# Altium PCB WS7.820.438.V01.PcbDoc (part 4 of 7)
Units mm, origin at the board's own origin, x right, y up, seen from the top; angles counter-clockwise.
Board outline 143.01 x 224 mm, 4 copper layers (Top Layer, G2, S3, Bottom Layer); 863 components, 638 nets, 2623 pads, 4664 vias.
Unrouted connection lines stored in the file: 16.
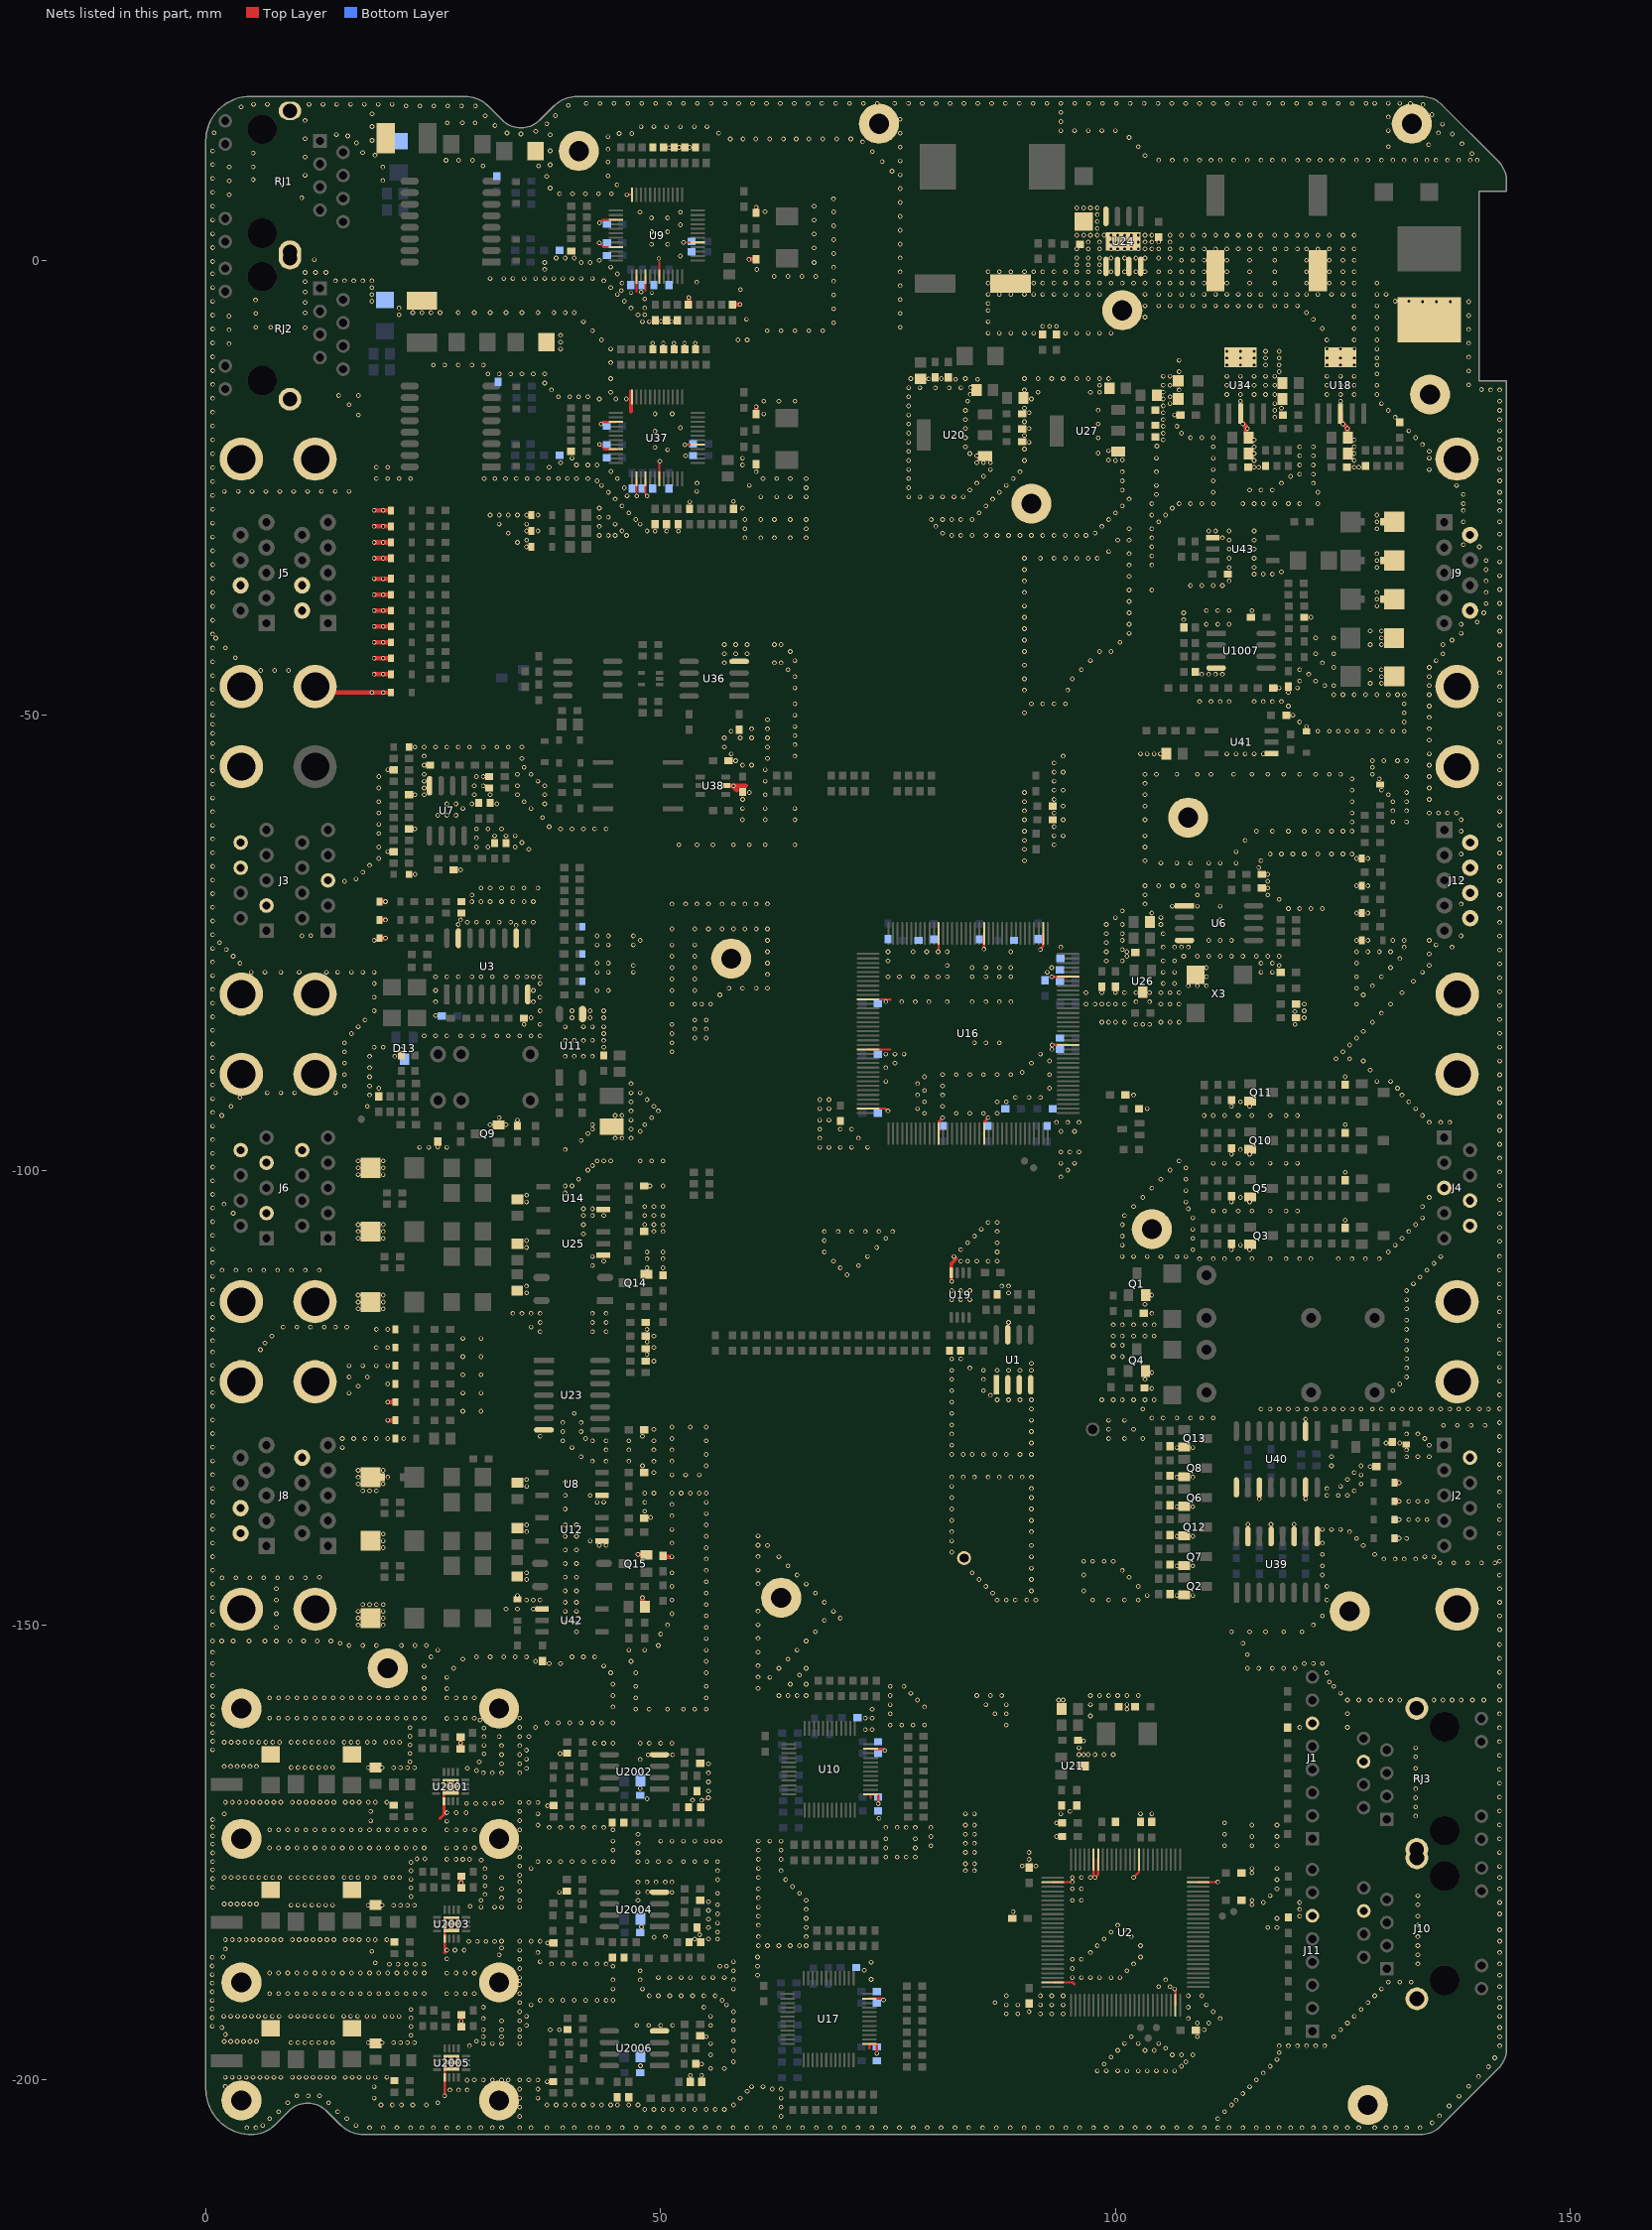
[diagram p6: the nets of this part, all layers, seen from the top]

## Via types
v1: diameter 0.508, hole 0.305, Top Layer to Bottom Layer, tented both sides, 4404 vias
v2: diameter 0.508, hole 0.3, Top Layer to Bottom Layer, tented both sides, 200 vias
v3: diameter 0.813, hole 0.508, Top Layer to Bottom Layer, tented both sides, 31 vias
v4: diameter 0.457, hole 0.305, Top Layer to Bottom Layer, tented both sides, 10 vias
v5: diameter 0.66, hole 0.406, Top Layer to Bottom Layer, tented both sides, 9 vias
v6: diameter 0.762, hole 0.406, Top Layer to Bottom Layer, tented both sides, 6 vias
v7: diameter 0.711, hole 0.406, Top Layer to Bottom Layer, tented both sides, 4 vias

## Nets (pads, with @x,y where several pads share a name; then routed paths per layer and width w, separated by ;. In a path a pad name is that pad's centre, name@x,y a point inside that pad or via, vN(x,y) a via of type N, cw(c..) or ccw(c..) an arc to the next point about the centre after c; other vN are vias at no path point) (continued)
GND: (continued)
  other v1: 4.5,-205.25 5.5,-205.25 18,-205.25 19.5,-205.25 21,-205.25 22.5,-205.25 23.75,-205.25 25,-205.25 26.5,-205.25 27.75,-205.25 29,-205.25 30.25,-205.25 31.5,-205.25 32.5,-205.25 34.5,-205.25 35.75,-205.25 37.5,-205.25 39.25,-205.25 40.5,-205.25 42.25,-205.25 43,-205.25 44.25,-205.25 45.774,-205.25 47.298,-205.25 48.822,-205.25 50.346,-205.25 51.87,-205.25 53.394,-205.25 54.918,-205.25 56.442,-205.25 57.966,-205.25 59.49,-205.25 61.014,-205.25 62.538,-205.25 64.062,-205.25 65.586,-205.25 67.11,-205.25 68.634,-205.25 70.158,-205.25 71.682,-205.25 73.206,-205.25 74.73,-205.25 76.254,-205.25 77.778,-205.25 79.302,-205.25 80.826,-205.25 82.35,-205.25 83.874,-205.25 85.398,-205.25 86.922,-205.25 88.446,-205.25 89.97,-205.25 91.494,-205.25 93.018,-205.25 94.542,-205.25 96.066,-205.25 97.59,-205.25 99,-205.25 100.638,-205.25 102.162,-205.25 103.686,-205.25 105.21,-205.25 106.734,-205.25 108.258,-205.25 109.75,-205.25 111.25,-205.25 112.5,-205.25 114,-205.25 115.5,-205.25 116.75,-205.25 118,-205.25 119.25,-205.25 120.5,-205.25 121.75,-205.25 123,-205.25 124.25,-205.25 125.5,-205.25 126.75,-205.25 128.5,-205.25 129.75,-205.25 130.75,-205.25 132,-205.25 133.5,-205.25 6.25,-205 16.5,-205 134.811,-204.714 7,-204.25 15.5,-204.25 111.25,-204.25 34.5,-204 63.25,-204 135.61,-203.941 8,-203.5 14.5,-203.5 112,-203.5 48.25,-203.25 49.25,-203.25 50.25,-203.25 51.25,-203.25 52.5,-203.25 53.75,-203.25 55,-203.25 56,-203.25 57,-203.25 34.5,-203 63.25,-203 136.687,-202.864 19.25,-202.75 20.5,-202.75 21.5,-202.75 22.75,-202.75 24.25,-202.75 37.5,-202.75 38.5,-202.75 39.5,-202.75 40.5,-202.75 41.5,-202.75 42.5,-202.75 43.5,-202.75 44.5,-202.75 45.25,-202.75 46.5,-202.75 47.5,-202.75 58,-202.75 112.75,-202.75 9,-202.5 13.5,-202.5 25.5,-202.5 113.25,-202.25 18.5,-202 34.5,-202 36.5,-202 58.75,-202 63.25,-202 137.765,-201.786 10,-201.75 11.25,-201.75 12.5,-201.75 26.25,-201.75 114,-201.5 59.5,-201.25 26.839,-201.107 27.784,-201.107 28.729,-201.107 34.5,-201 36.5,-201 62.25,-201 63.25,-201 18.5,-200.75 60,-200.75 61.25,-200.75 114.75,-200.75 2.118,-200.726 138.843,-200.708 37.52,-200.204 28.719,-200.02 29.5,-200 30.5,-200 31.5,-200 32.5,-200 33.25,-200 34.5,-200 35.5,-200 36.5,-200 115.5,-200 2.143,-199.71 2.905,-199.71 3.667,-199.71 4.429,-199.71 5.191,-199.71 5.953,-199.71 6.715,-199.71 7.477,-199.71 8.239,-199.71 9.501,-199.71 10.263,-199.71 11.025,-199.71 11.787,-199.71 12.549,-199.71 13.311,-199.71 14.073,-199.71 15.335,-199.71 16.097,-199.71 16.859,-199.71 17.871,-199.71 18.633,-199.71 19.895,-199.71 139.92,-199.631 53.25,-199.5 54.5,-199.5 116.25,-199.25 98,-199 99,-199 100.25,-199 101.25,-199 102.5,-199 103.5,-199 104.5,-199 105.5,-199 106.5,-199 55.5,-198.75 57,-198.75 140.998,-198.553 107.25,-198.5 117,-198.5 26.601,-198.454 27.363,-198.454 47.781,-198.437 54.5,-198.25 98.75,-198.25 58,-198 107.75,-198 117.75,-197.75 26.601,-197.692 27.363,-197.692 141.702,-197.578 99.5,-197.5 55.5,-197.25 106.25,-197.25 107.25,-197.25 108.5,-197.25 118,-197 58,-196.75 100.25,-196.75 103.25,-196.75 104.25,-196.75 105.5,-196.5 29,-196.25 118,-196.25 119,-196.25 120,-196.25 121,-196.25 122,-196.25 123,-196.25 142.25,-196.25 30.5,-196 31.5,-196 32.5,-196 34.5,-196 55.5,-196 101,-196 102.5,-196 104.75,-196 17.846,-195.914 19.37,-195.914 20.632,-195.914 21.394,-195.914 22.156,-195.914 22.918,-195.914 9.374,-195.9 10.136,-195.9 10.898,-195.9 11.66,-195.9 12.422,-195.9 13.184,-195.9 13.946,-195.9 2.016,-195.773 2.727,-195.773 3.438,-195.773 4.15,-195.773 4.861,-195.773 5.572,-195.773 29.75,-195.75 58,-195.75 30.5,-195.25 32.5,-195.25 34.5,-195.25 55,-195.25 101.75,-195.25 109,-195.25 124,-195.25 142.25,-195.25 22.562,-195.082 2.143,-195.011 30.5,-194.5 32.5,-194.5 34.5,-194.5 37.85,-194.5 38.866,-194.5 58,-194.5 109.75,-194.5 124.75,-194.5 1.762,-194.249 142.25,-194.25 22.562,-194.137 0.699,-194.092 35.25,-194 47.375,-193.992 48.687,-193.992 50,-193.992 51.312,-193.992 55.5,-194 109,-193.75 110.25,-193.75 125.5,-193.75 32.5,-193.5 34.5,-193.5 58,-193.5 30.5,-193.25 108,-193.25 111.5,-193.25 22.562,-193.192 0.699,-193.147 1.965,-193.004 2.727,-193.004 3.489,-193.004 4.251,-193.004 5.013,-193.004 5.775,-193.004 6.537,-193.004 7.299,-193.004 8.061,-193.004 9.323,-193.004 10.085,-193.004 10.847,-193.004 11.609,-193.004 12.371,-193.004 13.133,-193.004 13.895,-193.004 15.157,-193.004 15.919,-193.004 16.681,-193.004 17.693,-193.004 18.455,-193.004 19.717,-193.004 20.479,-193.004 21.241,-193.004 35.25,-193 55.5,-193 126.25,-193 142.25,-193 88,-192.75 89.25,-192.75 91.75,-192.75 93,-192.75 94.25,-192.75 34.5,-192.5 58,-192.5 90.5,-192.5 110.75,-192.5 127,-192.25 22.562,-192.247 0.699,-192.202 30.5,-192 54.75,-192 108,-192 142.25,-192 35.75,-191.75 57.25,-191.75 88,-191.75 89.25,-191.75 91.75,-191.75 93,-191.75 94.25,-191.75 110,-191.75 34.5,-191.5 86.75,-191.5 127.75,-191.5 0.699,-191.257 36.75,-191.25 38,-191.25 39.25,-191.25 40.5,-191.25 41.75,-191.25 43,-191.25 44,-191.25 44.75,-191.25 56.75,-191.25 142.25,-191 48.75,-190.75 49.75,-190.75 51,-190.75 52.25,-190.75 53.5,-190.75 54.75,-190.75 56,-190.75 88,-190.75 91.75,-190.75 93,-190.75 94.25,-190.75 108,-190.75 109.5,-190.75 128.5,-190.75 7,-190.5 8,-190.5 9,-190.5 10,-190.5 11,-190.5 12,-190.5 13,-190.5 14,-190.5 15,-190.5 16,-190.5 17,-190.5 18,-190.5 19,-190.5 20,-190.5 21,-190.5 22,-190.5 23,-190.5 24,-190.5 26.499,-190.517 27.5,-190.5 28.5,-190.5 29.5,-190.5 34.5,-190.5 0.699,-190.312 44.75,-190 48,-190 58,-190 129.25,-190 104.75,-189.75 106,-189.75 142.25,-189.75 34.5,-189.5 0.699,-189.367 130,-189.25 131.25,-189.25 132.5,-189.25 44.75,-189 47.75,-189 58,-189 105.5,-189 73.139,-188.961 34.5,-188.75 49.75,-188.75 51,-188.75 52.25,-188.75 53.25,-188.75 54.75,-188.75 55.75,-188.75 57,-188.75 95.25,-188.75 96.25,-188.75 97.25,-188.75 98.25,-188.75 99.5,-188.75 100.5,-188.75 60.65,-188.5 142.25,-188.5 0.699,-188.422 26.499,-188.267 7,-188.25 8,-188.25 9,-188.25 10,-188.25 11,-188.25 12,-188.25 13,-188.25 14,-188.25 15,-188.25 16,-188.25 17,-188.25 18,-188.25 19,-188.25 20,-188.25 21,-188.25 22,-188.25 23,-188.25 24,-188.25 27.5,-188.25 28.5,-188.25 29.5,-188.25 47.75,-188 58,-188 101.25,-188 72.377,-187.945 34.5,-187.75 95.25,-187.75 44.75,-187.5 56.5,-187.5 57.25,-187.5 60.65,-187.5 0.699,-187.477 20.179,-187.294 21.124,-187.294 22.069,-187.294 23.014,-187.294 23.959,-187.294 38,-187.25 39.25,-187.25 40.5,-187.25 41.75,-187.25 43,-187.25 44,-187.25 102,-187.25 133.25,-187.25 142.25,-187.25 18.633,-187.137 73.139,-187.056 36.75,-187 58,-187 34.5,-186.75 95.25,-186.75 96.25,-186.75 26.499,-186.685 0.699,-186.532 1.889,-186.502 60.65,-186.5 102.75,-186.5 32.25,-186.25 133.25,-186.25 36.5,-186 97.25,-186 142.25,-186 18.252,-185.867 34.5,-185.75 26.499,-185.74 27.388,-185.74 28.404,-185.74 2.143,-185.613 32.5,-185.5 60.75,-185.25 61.75,-185.25 63,-185.25 64.25,-185.25 65.25,-185.25 66,-185.25 98,-185.25 102.75,-185.25 133.25,-185.25 37.545,-184.944 28.902,-184.78 29.847,-184.78 30.792,-184.78 31.736,-184.78 32.5,-184.75 34.5,-184.75 35.75,-184.75 36.75,-184.75 142.25,-184.75 2.143,-184.597 2.905,-184.597 3.667,-184.597 4.429,-184.597 5.191,-184.597 5.953,-184.597 6.715,-184.597 7.477,-184.597 8.239,-184.597 9.501,-184.597 10.263,-184.597 11.025,-184.597 11.787,-184.597 12.549,-184.597 13.311,-184.597 14.073,-184.597 15.335,-184.597 16.097,-184.597 16.859,-184.597 17.871,-184.597 18.633,-184.597 19.895,-184.597 53.75,-184.5 55.25,-184.5 56.25,-184.5 98.75,-184.5 49.28,-184.32 50.5,-184.25 60.75,-184.25 66,-184.25 101.75,-184.25 133.25,-184.25 54.284,-184.041 56.25,-183.75 99.5,-183.75 101,-183.5 142.25,-183.5 55.249,-183.263 66,-183.25 116.75,-183.25 117.75,-183.25 26.601,-183.214 27.363,-183.214 47.883,-183.177 60.75,-183 100.25,-183 133.25,-183 56.25,-182.75 26.601,-182.452 27.363,-182.452 55.249,-182.318 66,-182.25 117.75,-182.25 60.75,-182 120.25,-182 133.25,-182 56.25,-181.75 142.25,-181.75 88.75,-181.5 55.249,-181.374 47.883,-181.272 66,-181.25 120.25,-181.25 30.25,-181 31.75,-181 32.5,-181 34.5,-181 60.75,-181 29.039,-180.914 17.846,-180.801 19.37,-180.801 20.632,-180.801 21.394,-180.801 22.156,-180.801 22.918,-180.801 9.374,-180.787 10.136,-180.787 10.898,-180.787 11.66,-180.787 12.422,-180.787 13.184,-180.787 13.946,-180.787 56.25,-180.75 115,-180.75 133.25,-180.75 2.016,-180.66 2.727,-180.66 3.438,-180.66 4.15,-180.66 4.861,-180.66 5.572,-180.66 116.25,-180.5 120.25,-180.5 142.25,-180.5 55.249,-180.429 30.25,-180.25 34.5,-180.25 47.5,-180.25 66,-180.25 95.25,-180.25 96.25,-180.25 115,-180.25 32.5,-180 60.75,-180 22.562,-179.842 117,-179.75 133.25,-179.75 30.69,-179.614 56.25,-179.5 65.25,-179.5 51.236,-179.392 38.866,-179.367 47.502,-179.367 48.572,-179.342 34.5,-179.25 32.5,-179 60.75,-179 95.25,-179 96.25,-179 117.75,-179 142.25,-179 22.562,-178.897 0.75,-178.826 64.5,-178.75 30.69,-178.669 34.5,-178.25 47.5,-178.25 48.5,-178.25 49.5,-178.25 50.5,-178.25 51.25,-178.25 56.25,-178 63.75,-178 117.75,-178 22.562,-177.952 0.75,-177.881 32.5,-177.75 60.75,-177.75 95.25,-177.75 96.25,-177.75 142.25,-177.75 2.016,-177.739 2.778,-177.739 3.54,-177.739 4.302,-177.739 5.064,-177.739 5.826,-177.739 6.588,-177.739 7.35,-177.739 8.112,-177.739 9.374,-177.739 10.136,-177.739 10.898,-177.739 11.66,-177.739 12.422,-177.739 13.184,-177.739 13.946,-177.739 15.208,-177.739 15.97,-177.739 16.732,-177.739 17.744,-177.739 18.506,-177.739 19.768,-177.739 20.53,-177.739 21.292,-177.739 30.69,-177.724 34.5,-177.5 115,-177.25 22.562,-177.007 56.25,-177 63.25,-177 83.5,-177 84.5,-177 0.75,-176.936 30.69,-176.779 35.75,-176.75 60.75,-176.75 115,-176.75 117.75,-176.75 142.232,-176.53 34.5,-176.5 89.75,-176.5 91.25,-176.5 83.5,-176.25 84.5,-176.25 22.562,-176.088 36.5,-176 37.75,-176 39,-176 40.25,-176 41.5,-176 42.75,-176 43.75,-176 44.75,-176 47.5,-176 48.5,-176 49.75,-176 51,-176 52.5,-176 53.75,-176 55,-176 56.25,-176 0.75,-175.991 30.279,-175.834 26.5,-175.75 27.5,-175.75 28.25,-175.75 29,-175.75 60.75,-175.75 63.25,-175.75 90.5,-175.75 23.197,-175.707 24.086,-175.707 34.5,-175.5 74.75,-175.5 76,-175.5 77,-175.5 78,-175.5 0.75,-175.047 142.232,-175.006 47.5,-175 83.5,-175 84.5,-175 90.5,-175 44.75,-174.75 60.75,-174.75 63.25,-174.75 7,-174.5 8,-174.5 9,-174.5 10,-174.5 11,-174.5 12,-174.5 13,-174.5 14,-174.5 15,-174.5 16,-174.5 17,-174.5 18,-174.5 19,-174.5 20,-174.5 21,-174.5 22,-174.5 23,-174.5 24,-174.5 26.499,-174.517 27.5,-174.5 28.5,-174.5 29.5,-174.5 34.5,-174.5 74.75,-174.5 78,-174.5 79.713,-174.25 112,-174.25 115,-174.25 117.75,-174.25 0.75,-174.102 47.5,-174 83.5,-174 84.5,-174 44.75,-173.75 50,-173.75 51.25,-173.75 52.5,-173.75 53.75,-173.75 55,-173.75 55.75,-173.75 56.5,-173.75 60.75,-173.75 62,-173.75 63.25,-173.75 74.75,-173.5 78,-173.5 142.232,-173.482 79.713,-173.25 93.5,-173.25 115,-173.25 117.75,-173.25 0.75,-173.157 47.5,-173 83.5,-173 84.5,-173 112,-173 26.499,-172.517 7,-172.5 8,-172.5 9,-172.5 10,-172.5 11,-172.5 12,-172.5 13,-172.5 14,-172.5 15,-172.5 16,-172.5 17,-172.5 18,-172.5 19,-172.5 20,-172.5 21,-172.5 22,-172.5 23,-172.5 24,-172.5 27.5,-172.5 28.5,-172.5 29.5,-172.5 34.5,-172.5 44.75,-172.5 37.75,-172.25 39,-172.25 40.25,-172.25 41.5,-172.25 42.75,-172.25 43.75,-172.25 74.75,-172.25 76,-172.25 77,-172.25 78,-172.25 79.713,-172.25 0.75,-172.212 36.5,-172 83.5,-172 84.5,-172 115,-172 117.75,-172 142.232,-171.958 93.5,-171.75 112,-171.75 26.499,-171.572 18.125,-171.516 34.5,-171.5 0.75,-171.389 74,-171.25 133,-171 2.016,-170.754 36.5,-170.75 83.5,-170.75 84.5,-170.75 94,-170.75 102.75,-170.75 104,-170.75 26.499,-170.627 27.515,-170.627 28.602,-170.627 18.125,-170.5 34.5,-170.5 95,-170.5 142.232,-170.434 133,-170 37.571,-169.859 28.658,-169.611 29.674,-169.611 30.711,-169.611 31.656,-169.611 32.5,-169.5 34.5,-169.5 35.5,-169.5 36.5,-169.5 2.143,-169.484 2.905,-169.484 3.667,-169.484 4.429,-169.484 5.191,-169.484 5.953,-169.484 6.715,-169.484 7.477,-169.484 8.239,-169.484 9.501,-169.484 10.263,-169.484 11.025,-169.484 11.787,-169.484 12.549,-169.484 13.311,-169.484 14.073,-169.484 15.335,-169.484 16.097,-169.484 16.859,-169.484 17.871,-169.484 18.633,-169.484 19.895,-169.484 53.5,-169.25 48.518,-169.1 133,-169 142.232,-168.91 55.25,-168.25 26.386,-168.049 27.402,-168.049 133,-168 47.756,-167.957 142.232,-167.386 26.386,-167.287 27.402,-167.287 55.25,-167.25 133,-166.75 30.5,-166.25 31.5,-166.25 32.5,-166.25 34.5,-166.25 55.25,-166.25 47.756,-166.052 29.75,-166 142.232,-165.862 28.75,-165.75 35.25,-165.75 133,-165.75 17.846,-165.688 19.37,-165.688 20.632,-165.688 21.394,-165.688 22.156,-165.688 22.918,-165.688 9.374,-165.674 10.136,-165.674 10.898,-165.674 11.66,-165.674 12.422,-165.674 13.184,-165.674 13.946,-165.674 2.016,-165.547 2.727,-165.547 3.438,-165.547 4.15,-165.547 4.861,-165.547 5.572,-165.547 32.5,-165.25 34.5,-165.25 55.25,-165.25 22.435,-165.039 30.055,-165.039 47.756,-164.782 35.25,-164.75 133,-164.5 142.232,-164.338 48.62,-164.282 51.312,-164.274 32.5,-164.25 34.5,-164.25 96,-164.25 96.5,-164.25 97,-164.25 97.75,-164.25 98.75,-164.25 99.75,-164.25 30.563,-164.165 38.937,-164.147 22.435,-164.12 35.25,-163.75 0.75,-163.713 96,-163.5 133,-163.5 32.5,-163.25 34.5,-163.25 30.563,-163.22 22.435,-163.175 42.75,-163 43.75,-163 44.75,-163 47.75,-163 48.75,-163 50,-163 51.25,-163 28.012,-162.961 2.016,-162.88 2.778,-162.88 3.54,-162.88 4.302,-162.88 5.064,-162.88 5.826,-162.88 6.588,-162.88 7.35,-162.88 8.112,-162.88 9.374,-162.88 10.136,-162.88 10.898,-162.88 11.66,-162.88 12.422,-162.88 13.184,-162.88 13.946,-162.88 15.208,-162.88 15.97,-162.88 16.732,-162.88 17.744,-162.88 18.506,-162.88 19.768,-162.88 20.53,-162.88 21.292,-162.88 142.232,-162.814 0.75,-162.768 96.5,-162.75 30.563,-162.275 22.435,-162.23 32.25,-162.25 34.5,-162.25 35.5,-162.25 0.75,-161.823 72.5,-161.5 73.25,-161.5 30.563,-161.331 142.232,-161.29 22.435,-161.285 34.5,-161.25 36.25,-161.25 120.25,-161.25 125.5,-161.25 75.25,-161 76.5,-161 77.75,-161 79,-161 88,-161 0.75,-160.878 37.5,-160.75 38.75,-160.75 40,-160.75 41.25,-160.75 42.5,-160.75 43.5,-160.75 44.75,-160.75 30.126,-160.467 7,-160.25 8,-160.25 9,-160.25 10,-160.25 11,-160.25 12,-160.25 13,-160.25 14,-160.25 15,-160.25 16,-160.25 17,-160.25 18,-160.25 19,-160.25 20,-160.25 21,-160.25 22,-160.25 23,-160.25 24,-160.25 26.499,-160.267 27.5,-160.25 28.5,-160.25 29.5,-160.25 34.5,-160.25 72.5,-160.25 73.25,-160.25 97.25,-160 0.75,-159.934 142.232,-159.766 75.25,-159.75 86.75,-159.75 88,-159.75 125.5,-159.75 47.25,-159.25 48.75,-159.25 50.75,-159.25 52.5,-159.25 53.75,-159.25 55,-159.25 73.25,-159.25 101.25,-159.25 0.75,-158.989 44.75,-159 79,-159 75.25,-158.75 85.75,-158.75 88,-158.75 97.25,-158.75 101.25,-158.75 78.25,-158.25 93.75,-158.25 94.25,-158.25 125.5,-158.25 126.75,-158.25 128,-158.25 129.25,-158.25 130.25,-158.25 131.25,-158.25 135,-158.25 136,-158.25 137,-158.25 138,-158.25 139.25,-158.25 140.5,-158.25 142.25,-158.25 26.499,-158.017 7,-158 8,-158 9,-158 10,-158 11,-158 12,-158 13,-158 14,-158 15,-158 16,-158 17,-158 18,-158 19,-158 20,-158 21,-158 22,-158 23,-158 24,-158 27.5,-158 28.5,-158 29.5,-158 47.25,-158 55,-158 0.75,-157.75 44.75,-157.75 63,-157.75 64,-157.75 65,-157.75 66,-157.75 75.25,-157.75 84.75,-157.75 86.25,-157.75 87.5,-157.75 97.25,-157.75 98.25,-157.75 99.25,-157.75 100.25,-157.75 101.25,-157.75 102.5,-157.75 77.5,-157.5 124.75,-157.5 24,-157 26.5,-157 60.706,-156.974 0.75,-156.75 47.25,-156.75 55,-156.75 75.25,-156.75 76.75,-156.75 124,-156.75 142.232,-156.718 44.75,-156.5 64.25,-156.5 66,-156.5 123.5,-156.25 24,-155.75 26.5,-155.75 62,-155.75 60.706,-155.724 0.75,-155.5 65.25,-155.5 44.5,-155.25 47.25,-155.25 55,-155.25 123.25,-155.25 142.232,-155.194 27.25,-154.75 63,-154.75 66,-154.75 114.5,-154.75 115.75,-154.75 117.25,-154.75 118.5,-154.75 119.75,-154.75 24,-154.5 43.75,-154.5 60.706,-154.474 0.75,-154.25 37.75,-154.25 39,-154.25 120.75,-154.25 121.75,-154.25 122.75,-154.25 36.25,-154 46.75,-154 55,-154 28.25,-153.75 64,-153.75 142.232,-153.67 24.75,-153.5 29.75,-153.5 31.25,-153.5 32.75,-153.5 34,-153.5 35.25,-153.5 40.25,-153.5 41.5,-153.5 42.75,-153.5 114.5,-153.25 0.75,-153 60.706,-152.974 25.5,-152.75 46.5,-152.75 48.25,-152.75 55,-152.75 65,-152.75 15.75,-152.25 17.25,-152.25 18.75,-152.25 21.5,-152.25 23,-152.25 24.25,-152.25 49.75,-152.25 142.232,-152.146 14.75,-152 114,-152 66,-151.75 55,-151.5 60.706,-151.474 50,-151 40.75,-150.75 67,-150.75 112.75,-150.75 114.75,-150.75 116.5,-150.75 118.5,-150.75 120.5,-150.75 142.25,-150.5 7.75,-150.25 55,-150.25 0.75,-150 16.75,-150 19.5,-150 50.75,-150 121.75,-150 60.706,-149.974 39.5,-149.75 40.75,-149.75 68,-149.5 16.75,-149.25 19.5,-149.25 69.75,-149.25 122.75,-149 142.25,-149 7.75,-148.75 51.25,-148.75 0.75,-148.498 16.75,-148.5 19.5,-148.5 39.5,-148.5 40.75,-148.5 69,-148.5 60.706,-148.474 33,-148.25 34.25,-148.25 17.25,-147.75 18,-147.75 18.75,-147.75 19.5,-147.75 39.5,-147.5 40.75,-147.5 68,-147.5 142.25,-147.5 7.75,-147.25 35.25,-147.25 36,-147.25 36.75,-147.25 51.25,-147.25 87,-147.25 88,-147.25 89,-147.25 90.25,-147.25 91.25,-147.25 97.5,-147.25 99.25,-147.25 101,-147.25 102.5,-147.25 123.25,-147.25 0.75,-146.995 34.25,-146.75 103.5,-146.75 106.75,-146.75 108.5,-146.75 67,-146.5 39.5,-146.25 90.75,-146.25 96.5,-146.25 7.75,-146 142.25,-146 51.25,-145.75 85.75,-145.75 102.5,-145.75 123.25,-145.75 0.75,-145.493 66,-145.5 60.706,-145.474 85,-145 90.75,-145 1.782,-144.808 3.306,-144.808 4.83,-144.808 6.354,-144.808 7.878,-144.808 9.402,-144.808 10.926,-144.808 12.5,-144.75 39.5,-144.75 101.5,-144.75 142.232,-144.526 65,-144.5 96.5,-144.5 122.75,-144.5 35.25,-144.25 51.25,-144.25 84.25,-144.25 0.75,-143.99 100.75,-144 60.706,-143.974 64,-143.5 106.75,-143.5 108.5,-143.5 122.75,-143.5 39.5,-143.25 135.666,-143.166 137.19,-143.166 138.714,-143.166 140.238,-143.166 141.708,-143.166 96.5,-143 97.5,-143 98.75,-143 99.75,-143 142.232,-143.002 129.5,-142.75 130.75,-142.75 131.75,-142.75 133,-142.75 63,-142.5 90.75,-142.5 134,-142.5 135,-142.5 0.75,-142.488 60.706,-142.474 122.75,-142.25 128.5,-142.25 82,-142 39.5,-141.75 19.5,-141.5 142.232,-141.478 44,-141.25 61.75,-141.25 90.75,-141.25 127.25,-141.25 60.706,-141.224 51.25,-141 122.75,-141 0.75,-140.986 19.5,-140.75 82,-140.75 126.5,-140.5 132,-140.5 39.5,-140.25 106.75,-140.25 108.5,-140.25 60.706,-140.208 19.5,-140 142.232,-139.954 82,-139.75 90.75,-139.75 125.75,-139.75 51.25,-139.5 122.75,-139.5 123.75,-139.5 124.75,-139.5 0.75,-139.483 39.5,-139 114.554,-138.938 117.094,-138.938 119.634,-138.938 82,-138.5 132.25,-138.43 133.25,-138.43 134.25,-138.43 142.232,-138.43 48.895,-138.176 51.25,-138 0.75,-137.981 39.5,-137.25 90.75,-137.25 106.75,-137 108.5,-137 142.232,-136.906 51.25,-136.75 0.75,-136.479 132.25,-136.398 133.25,-136.398 134.25,-136.398 82,-136 39.5,-135.75 123.25,-135.75 124.5,-135.75 125.5,-135.75 49.25,-135.5 51.25,-135.5 52.25,-135.5 53.25,-135.5 54.25,-135.5 142.232,-135.382 17.25,-135.25 18,-135.25 18.75,-135.25 126.25,-135.25 90.75,-135 123.25,-135 0.75,-134.976 124.75,-134.75 16.75,-134.5 127,-134.5 39.5,-134.25 125.5,-134 142.232,-133.858 16.75,-133.75 82,-133.75 83.25,-133.75 84.5,-133.75 86,-133.75 88.5,-133.75 90.75,-133.75 106.75,-133.75 108.5,-133.75 51.25,-133.5 52.75,-133.5 54.25,-133.5 127,-133.5 0.75,-133.474 49.25,-133.25 126.25,-133.25 16.75,-133 19.5,-133 128.016,-132.588 55,-132.5 123.75,-132.5 127,-132.5 142.232,-132.334 42.5,-132 44,-132 46.5,-132 49.25,-132 51.25,-132 0.75,-131.971 41.25,-131.5 123.75,-131.5 132,-131.5 133.25,-131.5 134.5,-131.5 55,-131.25 82,-131.25 83.25,-131.25 84.25,-131.25 85.5,-131.25 88,-131.25 90.75,-131.25 142.232,-130.81 44,-130.75 46.5,-130.75 49.25,-130.75 51.25,-130.75 132,-130.75 40.25,-130.5 106.75,-130.5 108.5,-130.5 0.75,-130.469 82,-130.25 134.5,-130.25 90.75,-130 129.75,-130 131.25,-130 39.25,-129.75 42.5,-129.75 44,-129.75 46.5,-129.75 55,-129.75 21.75,-129.5 41.75,-129.5 51.25,-129.5 99.25,-129.5 101,-129.5 103,-129.5 134,-129.5 142.232,-129.286 36.75,-129.25 82,-129 132,-129 133.25,-129 0.75,-128.967 41.25,-128.75 90.75,-128.75 99.25,-128.5 102,-128.5 51.25,-128.25 55,-128.25 136.047,-128.053 137.571,-128.053 139.095,-128.053 140.619,-128.053 82,-128 142.232,-127.762 39.25,-127.75 41.25,-127.75 90.75,-127.5 99.25,-127.5 101,-127.5 0.75,-127.464 120.904,-127.381 104,-127.25 105.25,-127.25 106.75,-127.25 108.25,-127.25 109.5,-127.25 110.75,-127.25 40.5,-126.75 82,-126.75 28.25,-126.5 30.25,-126.5 90.75,-126.25 103,-126.25 116,-126.25 117,-126.25 118,-126.25 119,-126.25 120,-126.25 121,-126.25 122,-126.25 123,-126.25 124,-126.25 125,-126.25 126,-126.25 127,-126.25 128.25,-126.25 129.25,-126.25 130.5,-126.25 131.5,-126.25 132.5,-126.25 133.5,-126.25 134.75,-126.25 135.75,-126.25 136.75,-126.25 137.75,-126.25 138.75,-126.25 140,-126.25 141,-126.25 142.232,-126.238 0.75,-125.962 87,-125.25 88.25,-125.25 89.5,-125.25 90.75,-125.25 98.5,-125.25 99.75,-125.25 100.75,-125.25 102,-125.25 103.25,-125.25 104.25,-125.25 86.25,-124.75 142.232,-124.714 28.25,-124.5 30.25,-124.5 0.75,-124.46 82,-124.25 85.5,-124.25 130.5,-124.25 104,-124 131.25,-123.5 142.232,-123.19 85.5,-123 103.25,-123 0.75,-122.957 15.75,-122.75 132,-122.75 28.25,-122.5 30.25,-122.5 104,-122.25 82,-122 85.5,-122 87,-122 88.25,-122 89.5,-122 90.75,-122 84,-121.75 132,-121.75 142.232,-121.666 0.75,-121.455 90.75,-121.25 49.25,-121 82,-120.75 83,-120.75 132,-120.75 28.25,-120.5 30.25,-120.5 99.75,-120.5 100.75,-120.5 142.232,-120.142 0.75,-120 132,-119.75 18.75,-119.5 49.25,-119.5 99.75,-119.25 100.75,-119.25 0.75,-118.75 132,-118.75 142.232,-118.618 28.25,-118.5 30.25,-118.5 49.25,-118.25 99.75,-118.25 100.75,-118.25 102,-118.25 103.25,-118.25 104.25,-118.25 36.75,-117.75 42.5,-117.75 44,-117.75 0.75,-117.5 18.75,-117.5 132,-117.5 35.75,-117.25 142.232,-117.094 99.75,-117 100.75,-117 102,-117 103.25,-117 104.25,-117 36.75,-116.75 42.5,-116.75 44,-116.75 88.25,-116.75 132,-116.5 0.75,-116.194 33.75,-115.75 34.75,-115.75 35.75,-115.75 36.75,-115.75 42.5,-115.75 44,-115.75 104,-115.75 142.232,-115.57 16.75,-115.25 19.5,-115.25 132,-115.25 103.25,-114.75 0.75,-114.691 16.75,-114.5 19.5,-114.5 82,-114.25 83,-114.25 84,-114.25 132,-114.25 142.232,-114.046 16.75,-113.75 19.5,-113.75 104,-113.75 88.25,-113.5 82,-113.25 83,-113.25 84,-113.25 132,-113.25 0.75,-113.189 35.25,-112.75 87.5,-112.75 88.25,-112.75 142.232,-112.522 132.75,-112.5 133.5,-111.75 0.75,-111.687 70.5,-111.5 1.782,-111.002 3.306,-111.002 4.83,-111.002 6.354,-111.002 7.878,-111.002 9.402,-111.002 10.926,-111.002 12.45,-111.002 134.25,-111 142.232,-110.998 48.5,-110.75 50.25,-110.75 69.75,-110.75 42.5,-110.5 71.75,-110.5 135,-110.25 0.75,-110.184 69,-110 83,-110 83.75,-110 84.75,-110 86,-110 87,-110 48.5,-109.75 50.25,-109.75 109.25,-109.75 110.75,-109.75 112,-109.75 113.5,-109.75 115,-109.75 117,-109.75 118.75,-109.75 120.25,-109.75 121.5,-109.75 124.5,-109.75 126,-109.75 127.5,-109.75 129,-109.75 72.75,-109.5 82.25,-109.5 100.75,-109.5 102,-109.5 103.5,-109.5 105,-109.5 106.75,-109.5 107.75,-109.5 135.75,-109.5 142.232,-109.474 48.5,-109 50.25,-109 68,-109 87,-109 130,-109 83,-108.75 108.5,-108.75 112.75,-108.75 114.75,-108.75 0.75,-108.682 35.25,-108.5 73.75,-108.5 100.75,-108.25 113.75,-108.25 130.75,-108.25 83.75,-108 87,-108 142.251,-107.823 68,-107.75 16.75,-107.5 19.5,-107.5 74.75,-107.5 108.5,-107.5 131.5,-107.5 84.5,-107.25 100.75,-107.25 0.75,-107.179 41.5,-107 16.75,-106.75 19.5,-106.75 49.25,-106.75 50.25,-106.75 68,-106.75 69.5,-106.75 71,-106.75 72.5,-106.75 74,-106.75 75.5,-106.75 87,-106.75 132.25,-106.75 85.25,-106.5 108.5,-106.5 142.251,-106.299 16.75,-106 19.5,-106 41.5,-106 50.25,-106 100.75,-106 133,-106 86,-105.75 87,-105.75 0.75,-105.677 125.25,-105.5 108.5,-105.25 133.75,-105.25 41.5,-105 42.5,-105 50.25,-105 101,-105 142.251,-104.775 110.75,-104.5 112,-104.5 113.5,-104.5 115,-104.5 117,-104.5 118.75,-104.5 120,-104.5 41.5,-104.25 108,-104.25 0.75,-104.175 50.25,-104 102,-104 133.75,-104 35.25,-103.5 107.75,-103.5 112.75,-103.5 114.75,-103.5 142.251,-103.251 103,-103 113.75,-103 134.5,-103 0.75,-102.672 39.5,-102.5 107.75,-102.25 104,-102 39.5,-101.75 40.25,-101.75 50.25,-101.75 142.251,-101.727 0.75,-101.17 41,-101 105,-101 107.75,-101 94,-100.75 16.75,-100.5 19.5,-100.5 125.25,-100.25 142.251,-100.203 42,-100 94.75,-100 106,-100 16.75,-99.75 19.5,-99.75 107.75,-99.75 0.75,-99.667 42.5,-99.5 94,-99.25 95.5,-99.25 110.75,-99.25 112,-99.25 113.5,-99.25 115,-99.25 117,-99.25 118.75,-99.25 120,-99.25 16.75,-99 19.5,-99 47.75,-99 49,-99 50.25,-99 107,-99 142.251,-98.679 112.75,-98.25 114.75,-98.25 0.75,-98.165 94,-98 95,-98 96,-98 39.5,-97.75 113.75,-97.75 23.5,-97.5 24.5,-97.5 26.5,-97.5 67.5,-97.5 68.5,-97.5 69.75,-97.5 71,-97.5 72.75,-97.5 25.5,-97.473 142.251,-97.155 41.25,-96.75 0.75,-96.663 45,-96.5 45.75,-96.5 46.75,-96.5 67.5,-96.5 71.75,-96.5 47.75,-95.75 94,-95.75 95.5,-95.75 142.251,-95.631 42.5,-95.5 46.75,-95.5 67.5,-95.5 69.75,-95.5 71,-95.5 0.75,-95.16 31.25,-95 33,-95 48.25,-95 125.25,-95 93.5,-94.75 94.75,-94.75 96,-94.75 134.5,-94.75 135.75,-94.75 136.75,-94.75 34.25,-94.5 46.75,-94.5 67.5,-94.5 68.5,-94.5 32.25,-94.25 49,-94.25 142.251,-94.107 45,-94 45.75,-94 109.75,-94 110.75,-94 112,-94 113.5,-94 115,-94 117,-94 118.75,-94 120,-94 133.75,-94 79,-93.75 82.5,-93.75 84,-93.75 85.5,-93.75 87,-93.75 0.75,-93.658 46.75,-93.5 49.75,-93.5 67.5,-93.25 68.5,-93.25 78.25,-93.25 103.5,-93.25 133,-93.25 17.75,-93 49.25,-93 81,-93 112.75,-93 114.75,-93 142.251,-92.583 46.75,-92.5 79,-92.5 87,-92.5 88,-92.5 113.75,-92.5 132.25,-92.5 48.5,-92.25 67.5,-92.25 68.5,-92.25 0.75,-92.156 89,-92 90.5,-92 91.75,-92 18,-91.75 78.25,-91.75 81,-91.75 102,-91.75 131.5,-91.75 6.75,-91.5 8.25,-91.5 9.75,-91.5 14.25,-91.5 46.75,-91.5 47.75,-91.5 79,-91.25 142.251,-91.059 19,-91 92.75,-91 131,-91 15.25,-90.75 18,-90.75 81,-90.75 0.75,-90.653 46.75,-90.5 78.25,-90.5 74.75,-90.25 128.75,-90.25 130.25,-90.25 18,-89.75 79,-89.75 125.25,-89.75 142.251,-89.535 15.25,-89.5 81,-89.5 82.5,-89.5 84,-89.5 85.5,-89.5 87,-89.5 88.5,-89.5 92.75,-89.5 89.75,-89.25 0.75,-89.151 128,-89 18,-88.75 74.75,-88.75 15.25,-88.25 75.75,-88.25 90.75,-88.25 142.251,-88.011 92.75,-88 127.25,-88 124.25,-87.75 125.75,-87.75 0.75,-87.648 18,-87.5 20.75,-87.5 39.5,-87.5 40.5,-87.5 74.75,-87.25 75.75,-87.25 76.75,-87.25 91.75,-87.25 15.25,-87 51.25,-87 125,-87 21.5,-86.75 93.031,-86.737 18.5,-86.5 19.5,-86.5 142.251,-86.487 125.75,-86.25 0.75,-86.146 15.25,-86 51.25,-86 84.5,-86 85.75,-86 87.25,-86 39.5,-85.75 40.5,-85.75 41.5,-85.75 43.75,-85.75 53.75,-85.5 55,-85.5 126.5,-85.5 24,-85.25 25.25,-85.25 26.5,-85.25 28,-85.25 29.25,-85.25 30.5,-85.25 32,-85.25 33.25,-85.25 34.5,-85.25 35.75,-85.25 36.75,-85.25 16,-85 51.25,-85 142.251,-84.963 127.25,-84.75 0.75,-84.644 53.75,-84.5 55,-84.5 16.75,-84.25 39.5,-84.25 41.5,-84.25 42.5,-84.25 43.75,-84.25 35,-84 36.75,-84 51.25,-84 102.25,-84 103,-84 103.75,-84 119.75,-84 98.5,-83.75 99.25,-83.75 100,-83.75 101,-83.75 105,-83.75 106,-83.75 107,-83.75 128.25,-83.75 17.5,-83.5 53.75,-83.5 55,-83.5 142.251,-83.439 40.25,-83.25 43.75,-83.25 120.75,-83.25 0.75,-83.141 25.25,-83 129.25,-82.75 119.722,-82.576 18.5,-82.5 36.75,-82.5 40.25,-82.5 42.25,-82.5 43.75,-82.5 120.75,-82.5 142.251,-81.915 51.25,-81.75 53.75,-81.75 54.5,-81.75 55.5,-81.75 96.75,-81.75 97.75,-81.75 98.5,-81.75 99.25,-81.75 100,-81.75 101,-81.75 105,-81.75 106,-81.75 107,-81.75 120.75,-81.75 126.5,-81.75 130.25,-81.75 0.75,-81.639 25.25,-81.5 36,-81.5 74.75,-81.5 76.5,-81.5 78,-81.5 79.5,-81.5 81.5,-81.5 84.25,-81.5 85.75,-81.5 87.25,-81.5 88.5,-81.5 102.25,-81.5 103.75,-81.5 18.5,-81 36.75,-81 56.5,-80.75 127.25,-80.75 96.75,-80.5 98.5,-80.5 100,-80.5 101,-80.5 102.25,-80.5 103.75,-80.5 105,-80.5 106,-80.5 107,-80.5 131.5,-80.5 142.251,-80.391 25.25,-80.25 36,-80.25 43,-80.25 44.25,-80.25 51.25,-80.25 53.75,-80.25 0.75,-80.137 57.5,-80 59,-80 60.5,-80 61.75,-80 126.5,-80 108,-79.75 109,-79.75 110,-79.75 128.25,-79.75 18.5,-79.5 36.75,-79.5 105.25,-79.5 106.5,-79.5 132.75,-79.25 51.25,-79 53.75,-79 142.251,-78.867 25.25,-78.75 26.5,-78.75 27.75,-78.75 29.25,-78.75 30.25,-78.75 31.5,-78.75 33,-78.75 34.25,-78.75 35.25,-78.75 36,-78.75 36.75,-78.75 75,-78.75 76.25,-78.75 77.75,-78.75 79.25,-78.75 80.5,-78.75 81.5,-78.75 84.25,-78.75 85.75,-78.75 87.25,-78.75 88.5,-78.75 110,-78.75 126.5,-78.75 129.25,-78.75 0.75,-78.634 61.75,-78.5 5,-78.25 6.5,-78.25 8.25,-78.25 10.25,-78.25 13.25,-78.25 14.5,-78.25 16,-78.25 17.25,-78.25 18.5,-78.25 43,-78.25 44.25,-78.25 47,-78.25 92.5,-78.25 105.25,-78.25 106.5,-78.25 116,-78.25 117.25,-78.25 133.75,-78.25 51.25,-77.75 53.75,-77.75 84.25,-77.75 85.75,-77.75 87.25,-77.75 88.5,-77.75 93,-77.75 110,-77.75 130.25,-77.75 47,-77.5 81.5,-77.5 118,-77.5 134.5,-77.5 142.251,-77.343 3.75,-77.25 43,-77.25 44.25,-77.25 61.75,-77.25 116,-77.25 117.25,-77.25 126.5,-77.25 0.75,-77.132 75,-77 99,-77 100.75,-77 105.25,-77 106.5,-77 131.25,-76.75 3,-76.5 51.25,-76.5 53.75,-76.5 101.25,-76.5 107.5,-76.5 109,-76.5 110.25,-76.5 111.5,-76.5 112.75,-76.5 114,-76.5 115.5,-76.5 116.75,-76.5 118,-76.5 134.5,-76.25 61.75,-76 81.5,-76 88.5,-76 99,-76 101.25,-76 126.5,-76 127.75,-76 129,-76 130.25,-76 142.251,-75.819 2.25,-75.75 100.75,-75.75 0.75,-75.629 94,-75.5 105.25,-75.5 106.5,-75.5 107.25,-75.5 108,-75.5 131.75,-75.5 137,-75.5 43,-75.25 44.25,-75.25 47,-75.25 51.25,-75.25 53.75,-75.25 135.25,-75.25 1.5,-75 99,-75 18.5,-74.75 47.75,-74.75 61.75,-74.75 100.75,-74.75 110.25,-74.75 111.5,-74.75 112.75,-74.75 126.5,-74.75 127.75,-74.75 130.5,-74.75 131.75,-74.75 134.5,-74.75 142.251,-74.295 43,-74.25 44.25,-74.25 47,-74.25 138,-74.25 0.75,-74.127 99,-74 100.75,-74 105.25,-74 51.25,-73.5 53.75,-73.5 55.25,-73.5 56.75,-73.5 58,-73.5 59.25,-73.5 60.5,-73.5 61.75,-73.5 34.112,-73.101 27.75,-73 99,-73 100.75,-73 105,-73 142.251,-72.771 28.75,-72.75 29.75,-72.75 31,-72.75 32.25,-72.75 33.5,-72.75 35,-72.75 36,-72.75 0.75,-72.625 28,-72.5 111.5,-72.5 100,-72.25 105,-72.25 104,-71.75 126.5,-71.75 127.75,-71.75 100.75,-71.5 119,-71.25 120.25,-71.25 121.5,-71.25 122.75,-71.25 142.251,-71.247 0.75,-71.122 106.25,-71 109,-71 111.5,-71 51.25,-70.75 52.75,-70.75 54,-70.75 55.25,-70.75 56.75,-70.75 58,-70.75 59.25,-70.75 60.5,-70.75 61.75,-70.75 103.25,-70.75 138,-70.75 29.25,-70.5 30.25,-70.5 31.25,-70.5 32.5,-70.5 33.75,-70.5 35,-70.5 36,-70.5 118,-70.25 29.25,-69.75 103.25,-69.75 109,-69.75 116.75,-69.75 142.251,-69.723 0.75,-69.62 30.25,-69 31.25,-69 32.5,-69 33.75,-69 35,-69 36.5,-69 116.75,-69 103.25,-68.75 104.75,-68.75 106.25,-68.75 107.5,-68.75 109,-68.75 126.5,-68.75 127.75,-68.75 15.25,-68.25 116.75,-68.25 142.251,-68.199 0.75,-68.117 16.5,-68 138,-68 23,-67.5 116.75,-67.5 17.25,-67.25 28,-67 115.75,-66.75 142.251,-66.675 0.75,-66.615 18,-66.5 105,-66.25 106.75,-66.25 108.25,-66.25 110.25,-66.25 111.5,-66.25 113.25,-66.25 90,-66 103.25,-66 116,-66 19,-65.75 126.5,-65.75 127.75,-65.75 117,-65.25 118.25,-65.25 119.5,-65.25 120.75,-65.25 122.25,-65.25 123.75,-65.25 125,-65.25 126,-65.25 138,-65.25 142.251,-65.151 0.75,-65.113 20,-65 113.25,-65 35.5,-64.75 90,-64.75 19,-64.5 29.75,-64.5 31,-64.5 34,-64.5 103.25,-64.5 52,-64.25 54,-64.25 55.75,-64.25 58,-64.25 59.75,-64.25 61.5,-64.25 64.75,-64.25 93.25,-64.25 34.75,-64 90,-63.75 114.25,-63.75 142.251,-63.627 0.75,-63.61 29.75,-63.5 31.75,-63.25 33,-63.25 34,-63.25 93.25,-63.25 94.25,-63.25 103.25,-63.25 19,-63 90,-62.75 115.5,-62.75 117.25,-62.75 119,-62.75 120.75,-62.75 122.25,-62.75 123.75,-62.75 125,-62.75 126,-62.75 138,-62.75 23,-62.5 29.75,-62.5 31,-62.5 32.5,-62.5 39,-62.5 40.25,-62.5 41.5,-62.5 42.75,-62.5 44,-62.5 37.75,-62.25 93.25,-62.25 0.75,-62.108 142.251,-62.103 19,-62 126,-61.75 130.5,-61.75 132,-61.75 61.5,-61.5 64.75,-61.5 90,-61.5 94.25,-61.5 103.25,-61.5 138,-61.5 37,-61.25 25.5,-61 26.5,-61 27.5,-61 19,-60.75 93.25,-60.75 126,-60.75 134.5,-60.75 135.5,-60.75 136.5,-60.75 137.5,-60.75 0.75,-60.606 142.251,-60.579 90,-60.5 130.5,-60.5 132,-60.5 28.25,-60.25 35.75,-60.25 59,-60.25 61.5,-60.25 64.75,-60.25 94.25,-60 103.25,-60 26.5,-59.75 27.5,-59.75 29.25,-59.75 32,-59.75 37.25,-59.75 19,-59.5 35,-59.5 90,-59.5 126,-59.5 130.5,-59.5 132,-59.5 93.25,-59.25 134.5,-59.25 0.75,-59.103 142.251,-59.055 23,-58.75 24,-58.75 29.5,-58.75 31.25,-58.75 34.25,-58.75 37.25,-58.75 61.5,-58.75 103.25,-58.75 130,-58.75 90,-58.5 132,-58.5 93.25,-58.25 94.25,-58.25 126,-58.25 129.25,-58.25 19,-58 24,-58 134.5,-58 29.5,-57.75 30.5,-57.75 34.25,-57.75 37.25,-57.75 0.75,-57.601 142.251,-57.531 103.25,-57.5 24,-57.25 36.5,-57.25 61.5,-57.25 93.25,-57.25 126,-57 129,-57 19,-56.75 29.75,-56.75 30.5,-56.75 132,-56.75 134.5,-56.75 24,-56.5 34.25,-56.5 35.75,-56.5 103.25,-56.5 104.5,-56.5 106.75,-56.5 109,-56.5 110.5,-56.5 113,-56.5 115,-56.5 116.75,-56.5 118.5,-56.5 120.25,-56.5 122,-56.5 123.5,-56.5 124.75,-56.5 128.25,-56.5 93.25,-56.25 94.25,-56.25 0.75,-56.098 142.251,-56.007 20,-56 61.5,-56 35,-55.75 128.25,-55.75 24,-55.5 59,-55.5 60,-55.5 134.5,-55.5 93.25,-55.25 128.25,-55 129.5,-55 131,-55 132,-55 34.75,-54.75 61.75,-54.75 0.75,-54.596 24,-54.5 64.75,-54.5 94.25,-54.5 142.251,-54.483 57.75,-54.25 102.75,-54.25 103.5,-54.25 104.25,-54.25 104.925,-54.25 112.25,-54.25 113.25,-54.25 114.25,-54.25 115.25,-54.25 116.25,-54.25 134.5,-54.25 23,-53.5 24,-53.5 25.25,-53.5 26.5,-53.5 27.75,-53.5 29,-53.5 30.5,-53.5 32,-53.5 33.25,-53.5 34.75,-53.5 57,-53.5 61.75,-53.5 64.75,-53.25 0.75,-53.094 142.251,-52.959 134.5,-52.75 57,-52.5 58.75,-52.5 60,-52.5 61.75,-52.5 64.75,-52.25 0.75,-52 57.75,-51.75 122.25,-51.75 123.5,-51.75 124.5,-51.75 125.5,-51.75 126.5,-51.75 127.75,-51.75 129.25,-51.75 130.5,-51.75 131.75,-51.75 60,-51.5 61.75,-51.5 134.5,-51.5 142.251,-51.435 64.75,-51.25 121,-51.25 0.75,-51 120.25,-50.75 131.75,-50.75 61.75,-50.5 134.5,-50.25 0.75,-50 64.75,-50 119.5,-50 142.251,-49.911 90,-49.75 131.75,-49.75 119,-49 134.5,-49 64.75,-48.75 90.75,-48.75 92,-48.75 93.25,-48.75 94.5,-48.75 131.75,-48.75 0.75,-48.706 109.25,-48.5 110.5,-48.5 111.5,-48.5 112.5,-48.5 115.25,-48.5 116.25,-48.5 117.25,-48.5 118.25,-48.5 142.251,-48.387 124,-47.75 125,-47.75 126.25,-47.75 127.5,-47.75 128.75,-47.75 130,-47.75 131,-47.75 131.75,-47.75 134.5,-47.75 119,-47.5 90,-47.25 94.75,-47.25 0.75,-47.182 64.75,-47 118,-47 120,-47 142.251,-46.863 123,-46.75 124,-46.75 134.5,-46.75 128,-46.5 129.25,-46.5 120.25,-46.25 122,-46.25 90,-46 95.25,-46 64.75,-45.75 129.25,-45.75 134.5,-45.75 0.75,-45.658 109.5,-45.5 110.25,-45.5 111,-45.5 111.75,-45.5 121.25,-45.5 142.251,-45.339 6.039,-45.085 7.563,-45.085 9.087,-45.085 64,-45 96.25,-45 120.25,-45 128,-45 129.25,-45 124,-44.75 134.5,-44.75 90,-44.5 57,-44.25 62.5,-44.25 63.25,-44.25 122.75,-44.25 0.75,-44.134 64.75,-44 97.25,-44 135.25,-44 142.251,-43.815 3.241,-43.684 57,-43.25 58.25,-43.25 59.5,-43.25 122,-43.25 124,-43.25 136,-43.25 64.25,-43 90,-43 98.25,-43 99.5,-43 0.75,-42.61 2.164,-42.607 142.251,-42.291 57,-42.25 58.25,-42.25 59.5,-42.25 62.5,-42.25 63.25,-42.25 128,-42.25 129.25,-42.25 136,-42.25 100.5,-42 90,-41.75 137,-41.75 1.086,-41.529 122,-41.5 124,-41.5 129.25,-41.5 0.75,-41.086 101.5,-41 138,-41 142.251,-40.767 128,-40.75 129.25,-40.75 90,-40.5 101.5,-40 110,-40 111.25,-40 112.5,-40 138,-40 139.75,-39.75 0.75,-39.562 107.5,-39.5 90,-39.25 121.5,-39.25 142.251,-39.243 101.5,-38.75 107.5,-38.75 140.5,-38.75 110,-38.5 111.25,-38.5 112.5,-38.5 115,-38.5 0.75,-38.038 90,-38 128.75,-38 140.75,-37.75 142.251,-37.719 101.5,-37.5 128.75,-37.25 0.75,-36.514 90,-36.5 128.75,-36.5 140.75,-36.5 101.5,-36.25 104,-36.25 142.251,-36.195 108.25,-35.75 109.5,-35.75 110.75,-35.75 111.75,-35.75 90,-35.25 112.5,-35.25 140.75,-35.25 0.75,-34.99 101.5,-34.75 142.251,-34.671 115.25,-34.5 116.25,-34.5 117.25,-34.5 118.25,-34.25 90,-34 140.75,-34 112.5,-33.75 115.25,-33.75 128.75,-33.75 101.5,-33.5 104,-33.5 0.75,-33.466 142.251,-33.147 128.75,-33 140.75,-33 90,-32.75 91.75,-32.75 93.25,-32.75 94.5,-32.75 95.75,-32.75 97,-32.75 98,-32.75 112.5,-32.75 115.25,-32.75 104,-32.5 101.5,-32.25 128.75,-32.25 99.25,-32 0.75,-31.942 112.5,-31.75 115.25,-31.75 142.251,-31.623 35.25,-31.5 104,-31.5 140,-31.5 138.25,-31.25 34.25,-31 100.25,-30.75 101.5,-30.75 112.5,-30.75 115.25,-30.75 59.25,-30.5 61,-30.5 62.5,-30.5 64.25,-30.5 66,-30.5 104,-30.5 111.75,-30.5 0.75,-30.418 43.25,-30.25 44.25,-30.25 45,-30.25 46.25,-30.25 82,-30.25 83,-30.25 84.25,-30.25 85.75,-30.25 87,-30.25 88.25,-30.25 89.5,-30.25 90.75,-30.25 92,-30.25 93.25,-30.25 94.5,-30.25 95.75,-30.25 96.75,-30.25 142.251,-30.099 33.25,-30 81,-30 97.75,-30 49.378,-29.769 50.66,-29.769 51.943,-29.769 36.5,-29.75 45.75,-29.75 48.5,-29.75 110.25,-29.75 111,-29.75 112.5,-29.75 115.25,-29.75 59.25,-29.5 66,-29.5 101.5,-29.5 104,-29.5 128.75,-29.5 43.25,-29.25 80.25,-29.25 98.5,-29.25 32.25,-29 45,-29 47.75,-29 0.75,-28.894 104.75,-28.75 128.75,-28.75 138.25,-28.75 142.25,-28.75 47.25,-28.5 59.25,-28.5 61,-28.5 62.5,-28.5 64.25,-28.5 66,-28.5 79.75,-28.5 81,-28.5 82,-28.5 83,-28.5 84.25,-28.5 99.25,-28.5 43.25,-28.25 44.25,-28.25 31.25,-28 32.25,-28 33.25,-28 34.25,-28 36.5,-28 104,-28 105.5,-28 128.75,-28 46.5,-27.75 85,-27.75 100,-27.75 138.25,-27.5 142.25,-27.5 0.75,-27.37 43.25,-27.25 59,-27.25 106.25,-27.25 45.75,-27 85.75,-27 100.75,-27 104,-26.75 107,-26.75 108.25,-26.75 109.5,-26.75 110.75,-26.75 114,-26.75 115.25,-26.75 116.25,-26.75 117.5,-26.75 119,-26.75 120.25,-26.75 122.25,-26.75 138.25,-26.75 53.213,-26.543 58,-26.5 142.25,-26.5 45,-26.25 86.5,-26.25 101.5,-26.25 61,-26 62.75,-26 64.25,-26 66,-26 77.25,-26 78.5,-26 79.75,-26 81,-26 82.25,-26 83.25,-26 47.371,-25.908 48.514,-25.908 46.31,-25.893 0.75,-25.846 104.5,-25.75 138.25,-25.75 44.25,-25.5 87.25,-25.5 110.75,-25.5 122.25,-25.5 142.25,-25.5 2.032,-25.4 3.556,-25.4 5.08,-25.4 6.604,-25.4 8.128,-25.4 9.652,-25.4 11.176,-25.4 12.7,-25.4 14.224,-25.4 15.748,-25.4 53.975,-25.4 84,-25.25 100.75,-25.25 114.75,-25.25 116,-25.25 117.25,-25.25 46,-25 66,-25 77.25,-25 43.5,-24.75 59.75,-24.75 88,-24.75 104.5,-24.75 137.5,-24.75 54,-24.5 84.75,-24.5 118.25,-24.5 121.75,-24.5 0.75,-24.322 100.75,-24.25 110.75,-24.25 142.25,-24.25 18.75,-24 20,-24 21.25,-24 22.5,-24 38.75,-24 39.75,-24 40.75,-24 42,-24 45.25,-24 61.25,-24 62.75,-24 64.25,-24 66,-24 77.25,-24 88.75,-24 30.595,-23.996 31.773,-23.996 32.95,-23.996 34.128,-23.996 35.306,-23.996 36.484,-23.996 37.662,-23.996 85.5,-23.75 119.25,-23.75 120.25,-23.5 121.75,-23.5 60.5,-23.25 89.5,-23.25 100.75,-23.25 104.5,-23.25 44.534,-23.204 77.25,-23 86.25,-23 110.75,-23 134.5,-23 142.25,-23 0.75,-22.798 18.75,-22.75 37.75,-22.75 115.25,-22.75 115.75,-22.75 126.25,-22.75 126.75,-22.75 40.75,-22.5 42,-22.5 43,-22.5 59,-22.5 120.25,-22.5 121.75,-22.5 39,-22.25 84.75,-22.25 85.5,-22.25 86.25,-22.25 49.911,-22.098 77.25,-22 90,-22 100,-22 115.25,-22 126.25,-22 99.231,-21.945 100.755,-21.945 40.25,-21.75 59,-21.75 104.5,-21.75 110.75,-21.75 134.5,-21.75 142.25,-21.75 52.75,-21.5 84.75,-21.5 120.25,-21.5 121.75,-21.5 0.75,-21.274 84,-21.25 115.25,-21.25 126.25,-21.25 98.088,-21.183 77.25,-21 134.5,-21 99.231,-20.929 50.768,-20.821 90,-20.75 142.25,-20.75 49.371,-20.567 83.5,-20.5 110.75,-20.5 115.25,-20.5 120.25,-20.5 121.75,-20.5 126.25,-20.5 104.561,-20.421 133.75,-20.25 77.25,-20 90.5,-20 0.75,-19.75 105.25,-19.75 115.25,-19.75 126.25,-19.75 142.25,-19.75 98.088,-19.532 83.5,-19.5 108.25,-19.5 109.5,-19.5 110.75,-19.5 133,-19.5 90,-19.25 77.25,-19 105.25,-19 107.25,-19 49.371,-18.789 132.25,-18.75 142.25,-18.75 83.5,-18.5 90.5,-18.5 114.5,-18.5 52.165,-18.408 105.25,-18.25 106.75,-18.25 0.75,-18.226 98.088,-18.008 77.25,-18 114,-18 125,-18 90,-17.75 83.5,-17.5 105.25,-17.5 142.25,-17.5 117.5,-17.25 130.75,-17.25 16.764,-17.018 77.25,-17 106.5,-17 61.341,-16.891 49.371,-16.884 51.276,-16.884 90.5,-16.75 105.25,-16.75 0.75,-16.702 83.5,-16.5 98.088,-16.484 117.5,-16.5 130,-16.5 142.25,-16.5 90,-16.25 118.25,-16.25 77.25,-16 105.25,-16 15.748,-15.875 106,-15.75 117.5,-15.75 129.25,-15.75 61.341,-15.494 62.992,-15.494 64.77,-15.494 83.75,-15.5 113.75,-15.5 124.75,-15.5 142.25,-15.5 43.25,-15.25 45.085,-15.24 46.228,-15.24 90.75,-15.25 105.25,-15.25 0.75,-15.178 38.75,-15 40,-15 41,-15 42,-15 77.25,-15 106,-15 14.605,-14.859 16.764,-14.859 84.032,-14.743 112.25,-14.75 113.75,-14.75 115.25,-14.75 116.5,-14.75 117.5,-14.75 123.25,-14.75 124.75,-14.75 126.25,-14.75 128.75,-14.75 44.5,-14.5 91.5,-14.5 97.25,-14.5 98.25,-14.5 105.25,-14.5 38,-14.25 90,-14.25 107,-14.25 141.25,-14.25 142.25,-14.25 140.238,-14.21 77.25,-14 78.5,-14 80.19,-14.007 81.714,-14.007 83,-14 84.059,-13.976 98.25,-13.75 105.25,-13.75 106,-13.75 112.25,-13.75 113.75,-13.75 115.25,-13.75 116.5,-13.75 117.5,-13.75 123.25,-13.75 124.75,-13.75 126.25,-13.75 128.75,-13.75 138.841,-13.695 0.75,-13.654 37.25,-13.5 82.439,-13.081 84.836,-13.081 79.455,-13.026 80.853,-13.006 44.5,-13 77.5,-13 83.5,-13 90,-13 91.5,-13 93,-13 94.25,-13 95.75,-13 97,-13 98.25,-13 99.25,-13 105.25,-12.75 106,-12.75 112.25,-12.75 113.75,-12.75 115.25,-12.75 116.5,-12.75 117.5,-12.75 123.25,-12.75 124.75,-12.75 126.25,-12.75 31,-12.5 32.25,-12.5 33.5,-12.5 34.75,-12.5 36,-12.5 128.75,-12.5 107,-12.25 118,-12.25 138.841,-12.171 0.75,-12.13 25,-11.5 26.25,-11.5 27.75,-11.5 29.25,-11.5 30.5,-11.5 112.25,-11.5 113.75,-11.5 115.25,-11.5 116.5,-11.5 118,-11.5 123.25,-11.5 124.75,-11.5 126.25,-11.5 128.75,-11.5 44.5,-11.25 107,-11 112.25,-10.75 113.75,-10.75 115.25,-10.75 116.5,-10.75 118,-10.75 123.25,-10.75 124.75,-10.75 126.25,-10.75 128.75,-10.75 138.841,-10.647 0.75,-10.606 112.25,-10 113.75,-10 115.25,-10 116.5,-10 118,-10 39,-9.75 44.5,-9.75 123.25,-9.75 124.75,-9.75 126.25,-9.75 128.75,-9.75 2.54,-9.178 138.841,-9.123 0.75,-9.082 39,-9 43.5,-8.75 58.5,-8.75 59.5,-8.75 123.25,-8.75 126.25,-8.75 128.75,-8.75 39,-8.25 86,-8 87.25,-8 88.5,-8 90,-8 91,-8 94.5,-8 95.75,-8 97,-8 98.25,-8 99.5,-8 42.5,-7.75 61.722,-7.747 63.246,-7.747 64.77,-7.747 66.294,-7.747 67.818,-7.747 2.54,-7.654 138.841,-7.599 0.75,-7.558 122.75,-7.5 126.25,-7.5 128.75,-7.5 10.91,-7.424 7.112,-7.366 9.017,-7.366 76.331,-7.366 5.475,-7.361 92,-7.25 92.75,-7.25 93.5,-7.25 69.017,-6.877 41.5,-6.75 48,-6.75 48.75,-6.75 86,-6.75 121.75,-6.5 59.436,-6.477 103.25,-6.25 126.25,-6.25 128.75,-6.25 2.54,-6.13 138.841,-6.075 0.75,-6.034 21.25,-6 47.5,-6 48.25,-6 76.331,-5.842 5.475,-5.837 10.91,-5.773 22.75,-5.75 23.75,-5.75 24.75,-5.75 25.75,-5.75 27.75,-5.75 29.5,-5.75 31.25,-5.75 33,-5.75 34.75,-5.75 36.5,-5.75 38.25,-5.75 39.5,-5.75 40.5,-5.75 121,-5.75 86,-5.5 69.017,-5.353 21.25,-5.25 46.75,-5.25 48.25,-5.25 103.25,-5 104.75,-5 106,-5 107.25,-5 108.5,-5 109.75,-5 111,-5 112.25,-5 113.5,-5 114.75,-5 116,-5 117.5,-5 118.75,-5 120,-5 126.25,-5 128.75,-5 86,-4.75 10.91,-4.63 133.761,-4.551 135.285,-4.551 136.809,-4.551 138.841,-4.551 0.75,-4.51 46,-4.5 130.75,-4.5 132.25,-4.5 5.449,-4.376 76.331,-4.318 48.25,-4.25 69.017,-3.829 45.25,-3.75 86,-3.75 87.25,-3.75 88.5,-3.75 90,-3.75 91,-3.75 92,-3.75 93.25,-3.75 94.5,-3.75 95.75,-3.75 97,-3.75 98.25,-3.75 103.25,-3.75 104.75,-3.75 106,-3.75 107.25,-3.75 108.5,-3.75 109.75,-3.75 111,-3.75 112.25,-3.75 113.5,-3.75 114.75,-3.75 116,-3.75 117.5,-3.75 118.75,-3.75 120,-3.75 121,-3.75 122.25,-3.75 123.75,-3.75 125,-3.75 126.25,-3.75 128.75,-3.75 129.75,-3.75 10.91,-3.487 45.688,-3.32 58.769,-3.219 18.25,-3 44.5,-3 0.75,-2.986 76.331,-2.794 45.75,-2.5 86,-2.5 91,-2.5 92,-2.5 93.25,-2.5 94.5,-2.5 95.75,-2.5 97,-2.5 98.25,-2.5 99.5,-2.5 100.75,-2.5 102,-2.5 103.25,-2.5 104.75,-2.5 106,-2.5 107.25,-2.5 108.5,-2.5 109.75,-2.5 112.25,-2.5 114.75,-2.5 117.5,-2.5 121,-2.5 123.5,-2.5 125,-2.5 126.25,-2.5 128.75,-2.5 53.975,-2.413 10.91,-2.344 69.017,-2.305 14.25,-2.25 15.25,-2.25 16.25,-2.25 17.25,-2.25 18.25,-2.25 43.75,-2.25 31.25,-2 32.75,-2 39.25,-2 40.25,-2 41.25,-2 42.5,-2 62.484,-1.778 64.008,-1.778 65.532,-1.778 67.056,-1.778 0.75,-1.462 10.91,-1.328 12.053,-1.328 13.196,-1.328 76.331,-1.27 86,-1.25 87.25,-1.25 88.5,-1.25 90,-1.25 91,-1.25 92,-1.25 93.25,-1.25 94.5,-1.25 95.75,-1.25 97,-1.25 98.25,-1.25 99.5,-1.25 101,-1.25 102.25,-1.25 103.25,-1.25 104.75,-1.25 106,-1.25 107.25,-1.25 108.5,-1.25 109.75,-1.25 112.25,-1.25 114.75,-1.25 117.5,-1.25 121,-1.25 123.5,-1.25 125,-1.25 126.25,-1.25 60.579,-1.016 37.25,-1 69.017,-0.781 44.5,-0.75 95.75,-0.5 97,-0.5 98.25,-0.5 66.862,-0.254 37.25,-0.25 0.75,-0.141 43.25,0 107.25,0 108.5,0 109.75,0 112.25,0 114.75,0 117.5,0 121,0 123.5,0 125,0 126.25,0 11.926,0.069 39.5,0.25 40.5,0.25 76.331,0.254 95.75,0.25 97,0.25 98.25,0.25 99.5,0.25 101,0.25 102.25,0.25 103.25,0.25 104.75,0.25 106,0.25 52.165,0.464 69.017,0.743 95.75,1.25 97,1.25 98.25,1.25 99.5,1.25 100.25,1.25 101,1.25 101.75,1.25 102.5,1.25 103.25,1.25 104,1.25 104.75,1.25 106,1.25 107.25,1.25 108.5,1.25 109.75,1.25 111,1.25 112.25,1.25 113.5,1.25 114.75,1.25 116,1.25 117.5,1.25 118.75,1.25 120,1.25 121,1.25 122.25,1.25 123.5,1.25 125,1.25 126.25,1.25 66.862,1.374 0.75,1.383 48.99,1.734 50.768,1.734 76.331,1.778 97,2 98.25,2 99.5,2 100.25,2 101,2 101.75,2 102.5,2 103.25,2 104,2 104.75,2 106,2 69.017,2.267 95.75,2.75 96.5,2.75 97.25,2.75 98,2.75 98.75,2.75 99.5,2.75 100.25,2.75 101,2.75 101.75,2.75 102.5,2.75 103.25,2.75 104,2.75 106,2.75 107.25,2.75 108.5,2.75 109.75,2.75 111,2.75 112.25,2.75 113.5,2.75 114.75,2.75 116,2.75 117.5,2.75 118.75,2.75 120,2.75 121,2.75 122.25,2.75 123.5,2.75 125,2.75 126.25,2.75 66.862,2.898 0.75,2.907 48.99,3.131 50.768,3.131 76.331,3.302 98,3.5 69.017,3.791 52.165,3.893 98,4.25 66.862,4.422 0.75,4.431 48.99,4.655 50.768,4.655 76.331,4.826 98,5 47.72,5.29 52.165,5.29 61.468,5.334 69.017,5.315 95.75,5.75 96.5,5.75 97.25,5.75 98,5.75 66.862,5.946 0.75,5.955 76.331,6.35 69,6.75 10.541,6.858 2.565,7.205 38.875,7.308 40.304,7.308 41.732,7.308 43.161,7.308 44.59,7.308 0.75,7.479 76.331,7.874 37.859,7.943 45.202,8.291 2.565,8.729 19.435,8.763 5.195,8.857 0.75,9.003 37.478,9.213 44.214,9.279 10.91,9.34 76.331,9.398 75.431,9.786 2.565,10.253 5.195,10.254 19.435,10.239 30.468,10.356 36.564,10.356 37.846,10.507 0.75,10.527 44.214,10.803 74.353,10.864 76.331,10.922 26.404,10.991 27.801,10.991 29.325,10.991 104.75,11 106.25,11 107.75,11 109.25,11 110.5,11 111.5,11 113,11 114.5,11 116,11 117.25,11 118.5,11 120,11 121.25,11 122.5,11 123.75,11 125,11 126.5,11 127.75,11 129.25,11 130.5,11 131.75,11 133,11 134.25,11 135.25,11 136.5,11 137.75,11 139,11 139.75,11 10.91,11.349 103.25,11.5 18.606,11.549 139.181,11.723 5.195,11.778 17.234,11.829 73.275,11.942 0.75,12 37.846,12.031 44.214,12.2 50.935,12.377 52.035,12.402 53.21,12.402 76.331,12.446 102.5,12.5 130,12.5 134.428,12.7 138.104,12.8 16.55,12.896 72.198,13.019 18.276,13.175 57.658,13.335 59.055,13.335 60.452,13.335 61.976,13.335 63.5,13.335 64.897,13.335 66.294,13.335 67.818,13.335 69.342,13.335 70.898,13.335 10.91,13.358 101.5,13.5 44.214,13.597 15.609,13.658 14.339,13.81 37.846,13.809 34.64,13.879 137.026,13.878 45.434,13.926 46.831,13.926 56.388,13.97 76.331,13.97 33.116,13.981 0.902,14.013 135.5,14 36.266,14.184 94,14.25 95.5,14.25 97,14.25 98.5,14.25 100,14.25 130,14.25 18.276,14.699 47.847,14.688 49.244,14.688 50.641,14.688 52.165,14.688 53.689,14.688 55.086,14.688 31.785,14.804 135.948,14.956 37.485,14.997 26.543,15.113 28.194,15.113 29.591,15.113 94,15.25 10.91,15.367 76.331,15.494 130,15.75 30.707,15.882 38.43,15.9 134.809,16.002 18.276,16.096 94,16.25 3.88,16.862 22.009,16.96 23.533,16.96 25.057,16.96 26.581,16.96 28.105,16.96 29.629,16.96 39.853,17.009 133.818,17.111 5.245,17.137 6.769,17.137 11.341,17.137 12.865,17.137 14.389,17.137 15.913,17.137 17.437,17.137 18.961,17.137 20.485,17.137 41.821,17.238 43.345,17.238 44.869,17.238 46.393,17.238 47.917,17.238 49.441,17.238 50.965,17.238 52.489,17.238 54.013,17.238 55.537,17.238 57.061,17.238 58.585,17.238 60.109,17.238 61.633,17.238 63.157,17.238 64.681,17.238 66.205,17.238 67.729,17.238 69.253,17.238 70.777,17.238 72.301,17.238 73.825,17.238 75.717,17.238 77.241,17.238 78.765,17.238 80.289,17.238 81.813,17.238 83.337,17.238 84.861,17.238 86.385,17.238 87.909,17.238 89.433,17.238 90.957,17.238 92.481,17.238 94.005,17.238 95.529,17.238 97.053,17.238 98.577,17.238 100.101,17.238 101.625,17.238 103.149,17.238 104.673,17.238 106.197,17.238 107.721,17.238 109.245,17.238 110.769,17.238 112.293,17.238 113.817,17.238 115.341,17.238 116.865,17.238 118.389,17.238 119.913,17.238 121.437,17.238 122.961,17.238 124.485,17.238 126.009,17.238 127.533,17.238 132.421,17.238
